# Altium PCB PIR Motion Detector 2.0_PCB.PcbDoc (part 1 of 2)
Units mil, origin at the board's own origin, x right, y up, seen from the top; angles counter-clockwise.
Board outline 6000 x 2200 mil, 4 copper layers (Layer 1 - Top Layer, Layer 2 - GND, Layer 3 - PWR, Layer 4 - Bottom Layer), stack 61.634 mil thick; 136 components, 49 nets, 322 pads, 287 vias.
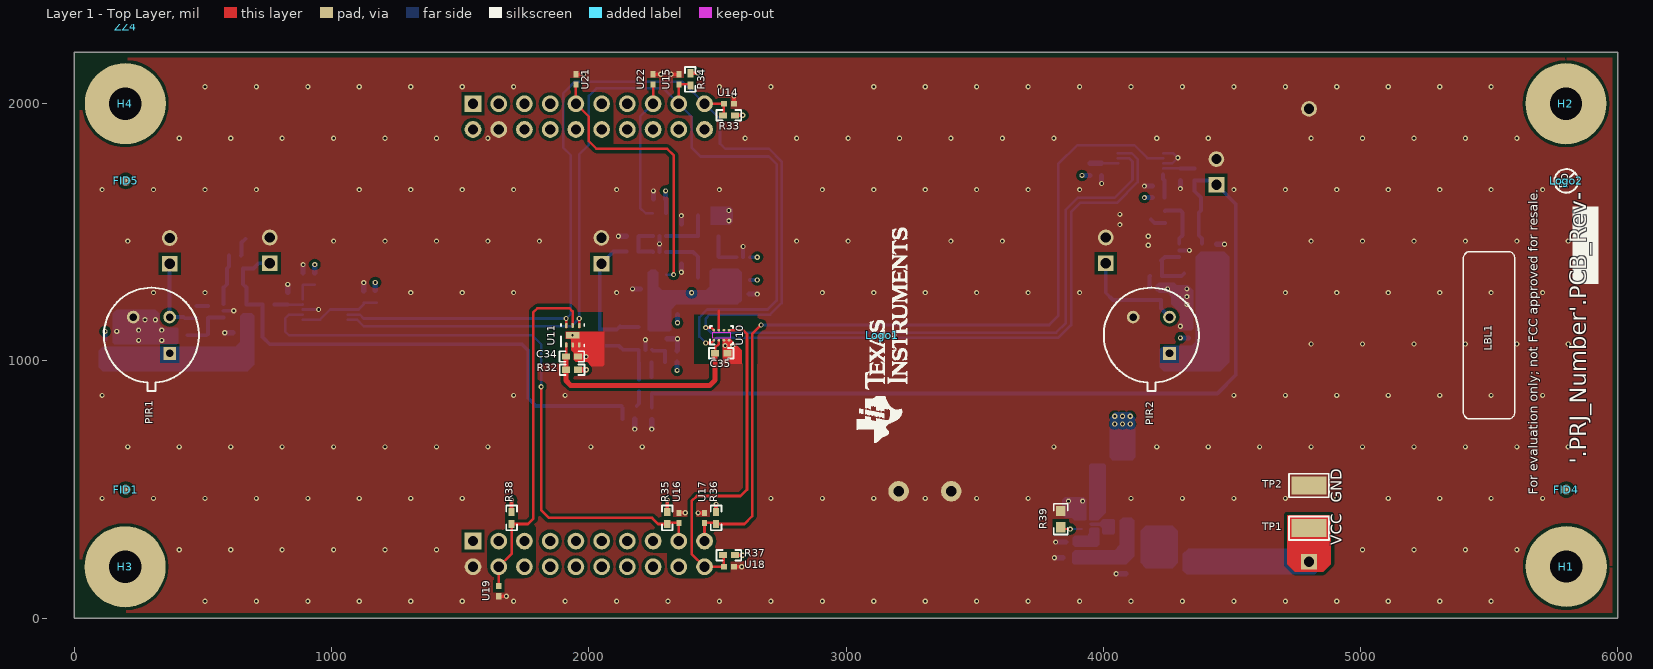
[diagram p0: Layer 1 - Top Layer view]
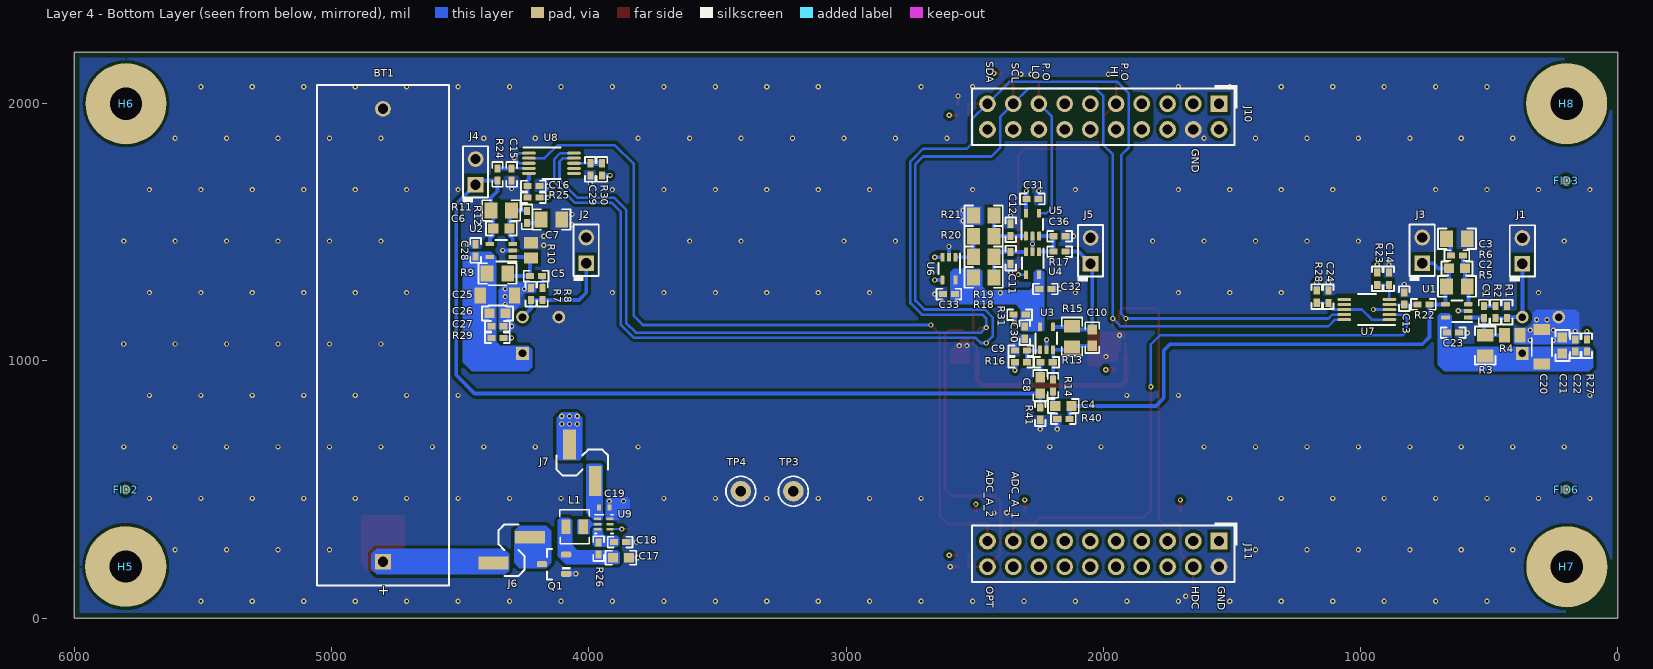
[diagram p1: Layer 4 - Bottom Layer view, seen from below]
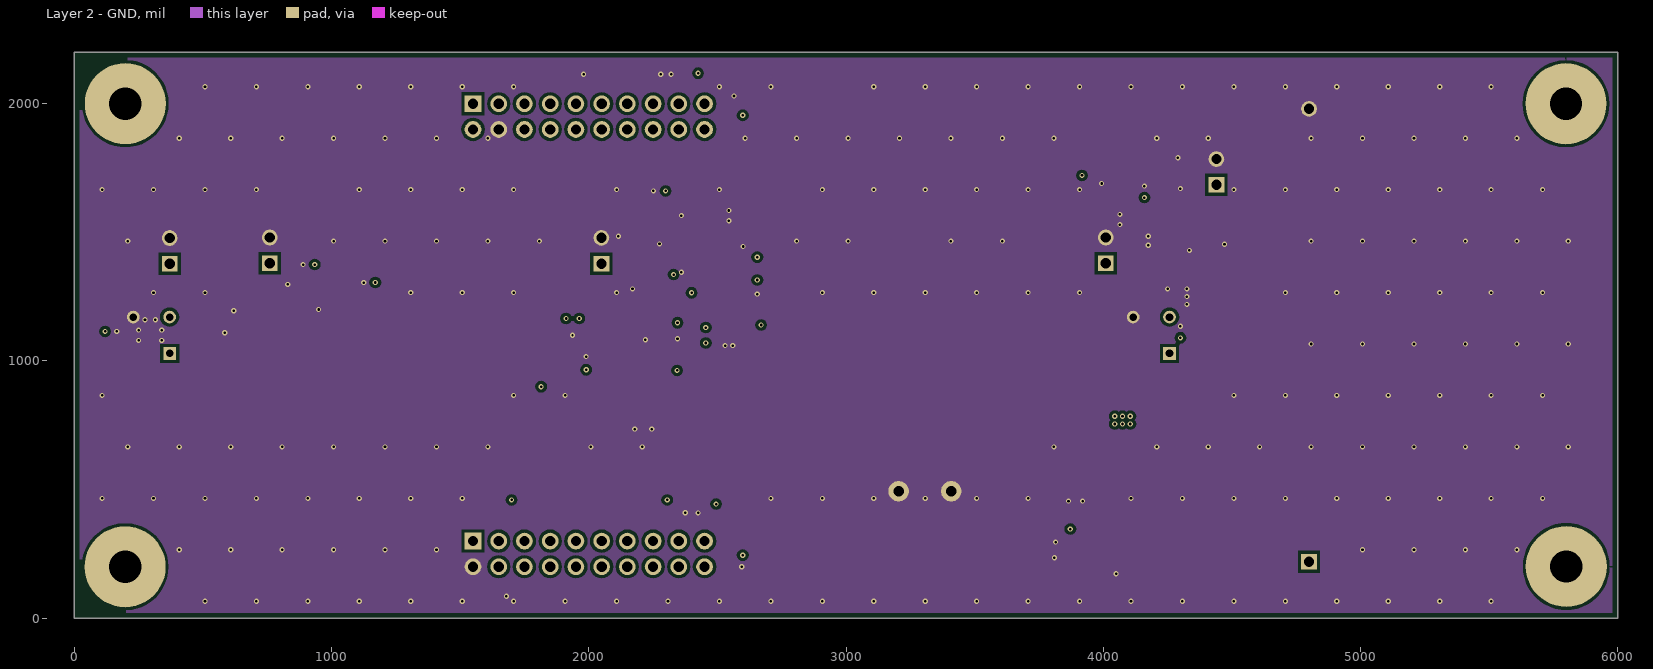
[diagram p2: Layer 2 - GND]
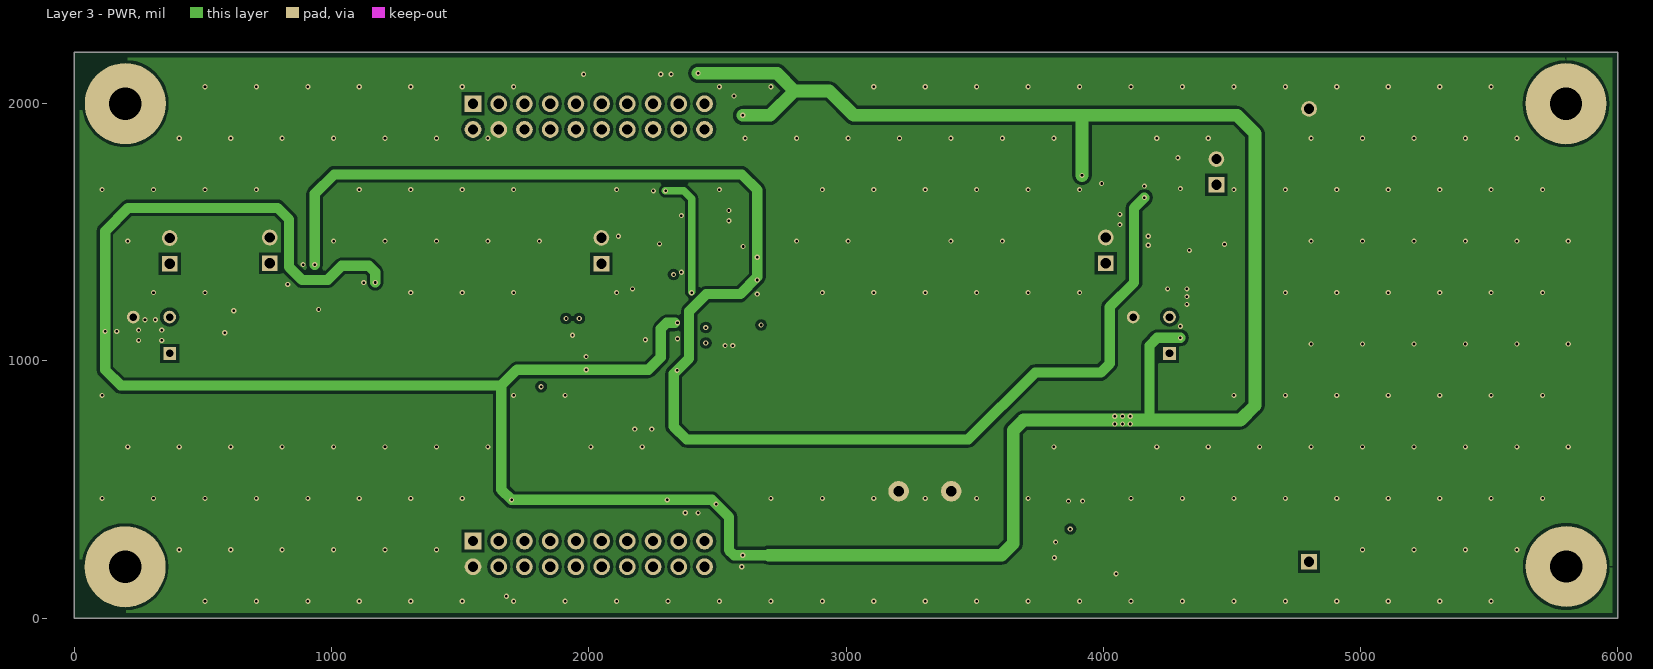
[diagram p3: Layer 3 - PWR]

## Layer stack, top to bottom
Top Solder: solder mask 0.4, Solder Resist, Dk 3.5
Layer 1 - Top Layer: signal copper 1.4
Dielectric 1: prepreg 7, FR-4, Dk 4.2
Layer 2 - GND: signal copper 1.417
Dielectric 2: core 42, FR-4, Dk 4.2
Layer 3 - PWR: signal copper 1.417
Dielectric 3: prepreg 7, FR-4, Dk 4.2
Layer 4 - Bottom Layer: signal copper 1.4
Bottom Solder: solder mask 0.4, Solder Resist, Dk 3.5

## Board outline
0,0 6000,0 6000,2200 0,2200

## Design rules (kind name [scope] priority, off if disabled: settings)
AcuteAngle [All] p1: minimum=4.50000000000000E+0001 checktracksonly=FALSE
AssemblyTestPointUsage [All] p1: valid=2
BoardOutlineClearance BoardOutlineClearance_MountingHoles [OnCopper and InComponentClass('Mounting Holes')] p1: gap=40
BoardOutlineClearance BoardOutlineClearance_Poly [OnCopper and IsPoly] p2: gap=20
BoardOutlineClearance [OnCopper and Not InComponentClass('Logo') and not InComponentClass('FiducialMark') and not InRegion(1000,500,4000,800) and not InPoly] p3: gap=20
Clearance Clearance_U10 [InComponent('U10')] p1: gap=4
Clearance Clearance_Keepouts [((IsTrack Or IsArc) And Not InPoly) And IsFree and IsKeepOut vs ((IsTrack Or IsArc) And Not InPoly) And IsFree and IsKeepOut] p2: gap=0
Clearance Clearance_Poly [InPolygon] p3: gap=12
Clearance [All] p4: gap=7.8
ComponentClearance ComponentClearance_MountingHoles_FiducialMarks [InComponentClass('Mounting Holes') vs InComponentClass('FiducialMark')] p1: gap=50 collisioncheckmode=3 verticalgap=10 showdistances=FALSE
ComponentClearance ComponentClearance_Shunt [InComponentClass('Header') vs InComponentClass('Shunt')] p2: gap=0 collisioncheckmode=3 verticalgap=0 showdistances=FALSE
ComponentClearance ComponentClearance_Logo [InComponentClass('Logo')] p3: gap=50 collisioncheckmode=3 verticalgap=10 showdistances=FALSE
ComponentClearance ComponentClearance_ScrewToNut [(HasFootprint('NY PMS 440 0025 PH')) vs (HasFootprint('Keystone_1902C'))] p4: gap=5 collisioncheckmode=3 verticalgap=10 showdistances=FALSE
ComponentClearance ComponentClearance_MountingHoles [InComponentClass('Mounting Holes')] p5: gap=100 collisioncheckmode=3 verticalgap=100000 showdistances=FALSE
ComponentClearance ComponentClearance_SmallPassives [HasFootprint('0201*') or HasFootprint('0402*') or HasFootprint('0508') or HasFootprint('0603*') or HasFootprint('0612') or HasFootprint('0805*') or HasFootprint('0815*') or HasFootprint('0830*') or HasFootprint('1206*') or HasFootprint('1210*') or HasFootprint('1808*') or HasFootprint('1812*') or HasFootprint('1825*') or HasFootprint('2010*') or HasFootprint('2220*') or HasFootprint('2225*') or HasFootprint('2512*') or HasFootprint('2728*') or HasFootprint('3518*') vs HasFootprint('0201*') or HasFootprint('0402*') or HasFootprint('0508') or HasFootprint('0603*') or HasFootprint('0612') or HasFootprint('0805*') or HasFootprint('0815*') or HasFootprint('0830*') or HasFootprint('1206*') or HasFootprint('1210*') or HasFootprint('1808*') or HasFootprint('1812*') or HasFootprint('1825*') or HasFootprint('2010*') or HasFootprint('2220*') or HasFootprint('2225*') or HasFootprint('2512*') or HasFootprint('2728*') or HasFootprint('3518*')] p6: gap=5 collisioncheckmode=3 verticalgap=10 showdistances=FALSE
ComponentClearance ComponentClearance_THtoSMT [IsThruComponent vs IsSMTComponent] p7: gap=20 collisioncheckmode=3 verticalgap=30 showdistances=FALSE
ComponentClearance ComponentClearance_THtoTH [IsThruComponent vs IsThruComponent] p8: gap=30 collisioncheckmode=3 verticalgap=30 showdistances=FALSE
ComponentClearance [All] p9: gap=10 collisioncheckmode=3 verticalgap=10 showdistances=FALSE
DiffPairsRouting [All] p1: maxlimit=100 minlimit=10 mostfreqgap=10 toplayer_minwidth=15 toplayer_maxwidth=15 toplayer_prefwidth=15 midlayer1_minwidth=15 midlayer1_maxwidth=15 midlayer1_prefwidth=15 midlayer2_minwidth=15 midlayer2_maxwidth=15 midlayer2_prefwidth=15 bottomlayer_minwidth=15 bottomlayer_maxwidth=15 bottomlayer_prefwidth=15 maxuncoupledlength=1000
FabricationTestPointUsage TestPointUsage [All] p1: valid=2 allowmultiple=FALSE
FabricationTestpoint Testpoint [All] p1: side=3 testpointundercomponent=TRUE minsize=40 maxsize=100 preferedsize=60 minholesize=0 maxholesize=40 preferedholesize=32 testpointgrid=1 allowsidetop=TRUE allowsidebottom=TRUE usegrid=TRUE gridtolerance=0.01
FanoutControl Fanout_LCC [IsLCC] p1: bgadir=Out bgaviamode=Centered fanoutstyle=Auto fanoutdirection=Alternating viagrid=1 // Fanout_LCC (Default Rule)
FanoutControl Fanout_BGA [IsBGA] p2: bgadir=Out bgaviamode=Centered fanoutstyle=Auto fanoutdirection=Alternating viagrid=1 // Fanout_BGA (Default Rule)
FanoutControl Fanout_Default [All] p4: bgadir=Out bgaviamode=Centered fanoutstyle=Auto fanoutdirection=Alternating viagrid=1 // Fanout_Default (Default Rule)
FanoutControl Fanout_Small [(CompPinCount < 5)] p5: bgadir=Out bgaviamode=Centered fanoutstyle=Auto fanoutdirection=OutThenIn viagrid=1 // Fanout_Small (Default Rule)
HoleSize [All] p1: absolutevalues=TRUE maxlimit=251 minlimit=7.87 maxpercent=80.000 minpercent=20.000
MinimumAnnularRing MinimumAnnularRing_ThermalPadVias [IsVia and InAnyComponent] p1: minimumring=5.91
MinimumAnnularRing [All] p2: minimumring=5
MinimumSolderMaskSliver MinimumSolderMaskSliver_Logo [InComponentClass('Logo') vs InComponentClass('Logo')] p1: minsoldermaskwidth=0.7
MinimumSolderMaskSliver [All] p2: minsoldermaskwidth=3.94
PlaneConnect [All] p1: planeconnectstyle=Relief reliefexpansion=10 reliefentries=4 reliefconductorwidth=10 reliefairgap=10
PolygonConnect [All] p1: connectstyle=Direct reliefconductorwidth=10 reliefentries=4 polygonreliefangle="90 Angle" airgapwidth=10
RoutingVias ThermalPadVias [IsVia and InAnyComponent] p1: holewidth=7.87 width=19.68 viastyle="Through Hole" minholewidth=7.87 minwidth=19.68 maxholewidth=12.99 maxwidth=23.62
RoutingVias [All] p2: holewidth=16 width=34 viastyle="Through Hole" minholewidth=7.87 minwidth=20 maxholewidth=40 maxwidth=65
SilkToBoardRegionClearance [Not ((IsComment or IsDesignator) And (Hide <> 'False')) and not InRegion(1000,500,4000,800)] p1:
SilkToSilkClearance SilkToSilkClearance_Pb-FreeLogo [(HasFootprint('Pb-Free_Overlay_Medium') OR HasFootprint('Pb-Free_Overlay_Small')) vs (HasFootprint('Pb-Free_Overlay_Medium') OR HasFootprint('Pb-Free_Overlay_Small'))] p1: silktosilkclearance=0
SilkToSilkClearance [All] p2: silktosilkclearance=4
SilkToSolderMaskClearance SilkToComponentPadClearance [IsPad and InAnycomponent] p1: minsilkscreentomaskgap=5 clearancetoexposedcopper=TRUE
SilkToSolderMaskClearance "Silk to Solder Mask Opening" [All] p2: minsilkscreentomaskgap=4 clearancetoexposedcopper=FALSE
SolderMaskExpansion [All] p1: expansion=1.97
Width [All] p1: maxlimit=100 minlimit=6 preferedwidth=10 checkconnectedcopper=TRUE
15 further rules are at their usual default settings.

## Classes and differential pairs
component class "PIR Motion Detector 2.0_PowerSheet": BT1 C17 C18 C19 C20 C21 C22 C23 C24 C25 C26 C27 C28 C29 C30 C31 C32 C33 C34 C35 C? J6 J7 J10 J11 L1 Q1 R26 R27 R28 R29 R30 R31 R32 R33 R34 R35 R36 R37 R38 R39 TP1 TP2 TP3 TP4 U9 U10 U11 U14 U15 U16 U17 U18 U19
component class "PIR Motion Detector 2.0_BlankSheet": ADC1 C1 C2 C3 C4 C5 C6 C7 C8 C9 C10 C11 C12 C13 C14 C15 C16 C36 C? J1 J2 J3 J4 J5 PIR1 PIR2 R1 R2 R3 R4 R5 R6 R7 R8 R9 R10 R11 R12 R13 R14 R15 R16 R17 R18 R19 R20 R21 R22 R23 R24 R25 R40 R41 R? U1 U2 U3 U4 U5 U6 U7 U8 U21 U22 U?
component class "Mounting Holes": H1 H2 H3 H4
component class Logo: Logo1
component class "PIR Motion Detector 2.0_EVM_Hardware": FID1 FID2 FID3 FID4 FID5 FID6 H1 H2 H3 H4 H5 H6 H7 H8 LBL1 Logo1 Logo2 Logo3 ZZ1 ZZ2 ZZ3 ZZ4
component class FiducialMark: FID1 FID2 FID3 FID4 FID5 FID6
component class AssemblyNote: ZZ1 ZZ2 ZZ3 ZZ4
component class Label: LBL1
component class Header: J1 J2 J3 J4 J5 J6 J7 J10 J11

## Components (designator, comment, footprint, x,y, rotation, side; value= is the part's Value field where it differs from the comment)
BT1 "2466" Keystone_2466 4800,1100 r90 bottom locked
C1 "C1005X5R1A105K050BB" 0402 520,1190 r90 bottom
C2 "06035A101FAT2A" 0603 625,1360 r180 bottom
C3 "C2012X5R1A336M125AC" 0805_HV 625,1475 r0 bottom
C4 "GRM188R61A106ME69D" 0603 2155,825 r180 bottom
C5 "C1005X5R1A105K050BB" 0402 4205,1330 r180 bottom
C6 "06035A101FAT2A" 0603 4340,1515 r180 bottom
C7 "C2012X5R1A336M125AC" 0805_HV 4145,1550 r0 bottom
C8 "GRM188R61A106ME69D" 0603 2245,905 r270 bottom
C9 "C1005X7R1H104K050BB" 0402 2320,1040 r0 bottom
C10 "GRM1885C1H151JA01D" 0603 2042.54,1090.75 r270 bottom
C11 "C1005X7R1H104K050BB" 0402 2360,1400 r270 bottom
C12 "C1005X7R1H104K050BB" 0402 2360,1510 r90 bottom
C13 "GRM1555C1H331FA01J" 0402 829.76,1242.62 r90 bottom
C14 "C1005X7R1H104K050BB" 0402 889.67,1319.63 r90 bottom
C15 "C1005X5R1A105K050BB" 0402 4300,1725 r270 bottom
C16 "C1005X7R1H104K050BB" 0402 4215,1680 r180 bottom
C17 "GRM188R60J106ME47D" 0603 3875,235 r180 bottom
C18 "GRM1555C1H331FA01J" 0402 3877.83,295.83 r180 bottom
C19 "GRM155R60G106ME44D" 0402_070 3940,430 r180 bottom
C20 "C3216X5R1A107M160AC" 1206_190 295,1055 r90 bottom
C21 "06033C105KAT2A" 0603 215,1060 r90 bottom
C22 "0402YC104KAT2A" 0402 165,1060 r90 bottom
C23 "0402YC104KAT2A" 0402 640,1110 r180 bottom
C24 "0402YC104KAT2A" 0402 1125,1249.63 r90 bottom
C25 "C3216X5R1A107M160AC" 1206_190 4355,1255 r180 bottom
C26 "06033C105KAT2A" 0603 4355,1185 r180 bottom
C27 "0402YC104KAT2A" 0402 4355,1135 r180 bottom
C28 "0402YC104KAT2A" 0402 4440,1430 r90 bottom
C29 "0402YC104KAT2A" 0402 3993.78,1745 r270 bottom
C30 "0402YC104KAT2A" 0402 2305,1110 r270 bottom
C31 "0402YC104KAT2A" 0402 2275,1630 r180 bottom
C32 "0402YC104KAT2A" 0402 2225,1280 r180 bottom
C33 "0402YC104KAT2A" 0402 2600,1260 r0 bottom
C34 "0402YC104KAT2A" 0402 1934.58,1017.21 r0 top
C35 "0402YC104KAT2A" 0402 2515,1030 r0 top
C36 "GRM1555C1H331FA01J" 0402 2170,1485 r180 bottom
FID1 "Fiducial" Fiducial10-20 200,500 r0 top
FID2 "Fiducial" Fiducial10-20 5800,500 r180 bottom
FID3 "Fiducial" Fiducial10-20 200,1700 r180 bottom
FID4 "Fiducial" Fiducial10-20 5800,500 r0 top
FID5 "Fiducial" Fiducial10-20 200,1700 r0 top
FID6 "Fiducial" Fiducial10-20 200,500 r180 bottom
H1 "NY PMS 440 0025 PH" "NY PMS 440 0025 PH"#1 5800,200.98 r0 top locked
H2 "NY PMS 440 0025 PH" "NY PMS 440 0025 PH"#1 5798.95,2000 r0 top locked
H3 "NY PMS 440 0025 PH" "NY PMS 440 0025 PH"#1 197.56,200 r0 top locked
H4 "NY PMS 440 0025 PH" "NY PMS 440 0025 PH"#2 198.95,2000 r0 top locked
H5 "1902C" Keystone_1902C 5800,200.98 r180 bottom locked
H6 "1902C" Keystone_1902C 5798.95,2000 r180 bottom locked
H7 "1902C" Keystone_1902C 197.56,200 r180 bottom locked
H8 "1902C" Keystone_1902C 198.95,2000 r180 bottom locked
J1 "HMTSW-102-07-G-S-240" SAMTEC_HMTSW-102-07-G-S-240 370.57,1427.95 r90 bottom
J2 "HMTSW-102-07-G-S-240" SAMTEC_HMTSW-102-07-G-S-240 4010,1430 r90 bottom
J3 "HMTSW-102-07-G-S-240" SAMTEC_HMTSW-102-07-G-S-240 760,1430 r90 bottom
J4 "HMTSW-102-07-G-S-240" SAMTEC_HMTSW-102-07-G-S-240 4440,1735 r90 bottom
J5 "HMTSW-102-07-G-S-240" SAMTEC_HMTSW-102-07-G-S-240 2049.19,1428.44 r90 bottom
J6 "87898-0204" Molex_87898-0204 4300,265 r90 bottom
J7 "87898-0204" Molex_87898-0204 4025,605 r0 bottom
J10 "PEC10DAAN" SULLINS_PEC10DAAN 2000,1950 r270 bottom locked
J11 "PEC10DAAN" SULLINS_PEC10DAAN 2000,250 r270 bottom locked
L1 "VLF302510MT-4R7M" VLF302510MT 4055,355 r180 bottom
LBL1 "Size: 0.65\" x 0.20 \"" Label_650x200 5500,1100 r90 top
Logo1 "Texas Instruments" TI_Stacked_Overlay_Small 3140,1100 r90 top
Logo2 "Pb-Free Symbol" Pb-Free_Overlay_Small 5800,1700 r90 top
Logo3 "FCC disclaimer" FCC_disclaimer 2350,3380 r0 top
PIR1 "IRA-E700ST0" Murata_IRA-E700ST0 300,1100 r90 top locked
PIR2 "IRA-E700ST0" Murata_IRA-E700ST0 4187,1100 r90 top locked
Q1 "SI2323DS" SOT-23 4135,210 r0 bottom
R1 "CRCW04021M30FKED" 0402 430,1190 r270 bottom
R2 "CRCW04020000Z0ED" 0402 475,1190 r90 bottom
R3 "RMCF0805JT15M0" 0805_HV 515,1060 r270 bottom
R4 "RMCF0805JT15M0" 0805L 410,1100 r0 bottom
R5 "RMCF0805JT15M0" 0805_HV 625,1290 r0 bottom
R6 "CRCW040240K2FKED" 0402 625,1410 r180 bottom
R7 "CRCW04021M30FKED" 0402 4225,1260 r270 bottom
R8 "CRCW04020000Z0ED" 0402 4180,1260 r90 bottom
R9 "RMCF0805JT15M0" 0805_HV 4355,1340 r0 bottom
R10 "RMCF0805JT15M0" 0805L 4225,1430 r270 bottom
R11 "RMCF0805JT15M0" 0805_HV 4340,1585 r0 bottom
R12 "CRCW040240K2FKED" 0402 4240,1560 r90 bottom
R13 "CRCW0402150KFKED" 0402 2220,995 r180 bottom
R14 "CRCW0402150KFKED" 0402 2195,905 r90 bottom
R15 "CRCW080510M0FKEA" 0805_HV 2121.65,1094.99 r90 bottom
R16 "CRCW04020000Z0ED" 0402 2320,995 r180 bottom
R17 "CRCW0402100KFKED" 0402 2170,1425 r0 bottom
R18 "RMCF0805JT15M0" 0805_HV 2465,1325 r0 bottom
R19 "RMCF0805JT15M0" 0805_HV 2465,1405 r180 bottom
R20 "RMCF0805JT15M0" 0805_HV 2465,1485 r0 bottom
R21 "RMCF0805JT15M0" 0805_HV 2465,1565 r180 bottom
R22 "CRCW0402100KFKED" 0402 755,1220 r0 bottom
R23 "CRCW04020000Z0ED" 0402 934.67,1319.63 r270 bottom
R24 "CRCW04020000Z0ED" 0402 4355,1725 r90 bottom
R25 "CRCW04020000Z0ED" 0402 4215,1635 r0 bottom
R26 "CRCW04020000Z0ED" 0402 3961.84,270.83 r90 bottom
R27 "CRCW040210R0FKED" 0402 120,1060 r270 bottom
R28 "CRCW040210R0FKED" 0402 1170,1250 r270 bottom
R29 "CRCW040210R0FKED" 0402 4355,1090 r0 bottom
R30 "CRCW040210R0FKED" 0402 3948.78,1745 r90 bottom
R31 "CRCW040210R0FKED" 0402 2325,1180 r180 bottom
R32 "CRCW040210R0FKED" 0402 1935,965.78 r180 top
R33 "CRCW040210K0JNED" 0402 2545,1955 r0 top
R34 "CRCW040210K0JNED" 0402 2395,2095 r90 top
R35 "CRCW040210K0JNED" 0402 2305,390 r90 top
R36 "CRCW040210K0JNED" 0402 2495,390 r90 top
R37 "CRCW040210K0JNED" 0402 2545,245 r0 top
R38 "CRCW040210K0JNED" 0402 1700,390 r90 top
R39 "CRCW060310M0JNEA" 0603 3835,385 r270 top
R40 "CRCW040210K0JNED" 0402 2155,775 r180 bottom
R41 "CRCW040210K0JNED" 0402 2245,795 r90 bottom
TP1 "5015" Testpoint_Keystone_Miniature 4800,350 r0 top
TP2 "5015" Testpoint_Keystone_Miniature 4800,515.51 r180 top
TP3 "5001" Keystone5001 3204.69,493.64 r90 bottom
TP4 "5001" Keystone5001 3409.03,493.64 r90 bottom
U1 "OPA349SA/3K" DCK0005A_N 625,1195 r0 bottom
U2 "OPA349SA/3K" DCK0005A_N 4340,1430 r0 bottom
U3 "TLV369IDCKR" DCK0005A_N 2220.12,1088.11 r90 bottom
U4 "TLV3691IDCKR" DCK0005A_N 2275,1380 r270 bottom
U5 "TLV3691IDCKR" DCK0005A_N 2275,1530 r90 bottom
U6 "TLV369IDCKR" DCK0005A_N 2600,1359.15 r270 bottom
U7 "ADS1114IDGSR" DGS0010A_N 975,1200 r0 bottom
U8 "ADS1114IDGSR" DGS0010A_N 4144.96,1768.61 r180 bottom
U9 "TPS610981DSER" DSE0006A 3941.62,366.15 r180 bottom
U10 "HDC1010YPAR" YPA0008AGAE 2515.79,1100 r90 top locked
U11 "OPT3002DNPR" DNP0006A 1937.34,1100 r90 top locked
U14 "TPD1E10B06DPYR" DPY0002A 2545,2000 r0 top
U15 "TPD1E10B06DPYR" DPY0002A 2350,2095 r90 top
U16 "TPD1E10B06DPYR" DPY0002A 2350,390 r90 top
U17 "TPD1E10B06DPYR" DPY0002A 2450,390 r90 top
U18 "TPD1E10B06DPYR" DPY0002A 2545,200 r0 top
U19 "TPD1E10B06DPYR" DPY0002A 1650,105 r270 top
U21 "TPD1E10B06DPYR" DPY0002A 1950,2095 r90 top
U22 "TPD1E10B06DPYR" DPY0002A 2250,2095 r90 top
ZZ1 "This Assembly Note is for PCB labels only" AssemblyNoteLabel 200,2600 r0 top
ZZ2 "These assemblies are ESD sensitive, ESD precautions shall be observed." AssemblyNote 200,2500 r0 top
ZZ3 "These assemblies must be clean and free from flux and all contaminants. Use of no clean flux is not acceptable." AssemblyNote 200,2400 r0 top
ZZ4 "These assemblies must comply with workmanship standards IPC-A-610 Class 2, unless otherwise specified." AssemblyNote 200,2300 r0 top

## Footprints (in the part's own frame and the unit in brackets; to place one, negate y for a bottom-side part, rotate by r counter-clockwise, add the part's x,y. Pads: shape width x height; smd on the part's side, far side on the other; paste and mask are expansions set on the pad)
0402 [mm] "0402 from SM-752 data"
  rect 0.8x0.6 smd: 1(-0.6,0) 2(0.6,0)
  silkscreen extent -1.22,-0.52 1.22,0.52, body extent -0.55,-0.3 0.55,0.3, height 0.6
0402_070 [mil] "SMD, 2-Leads, Body 1.2x0.7mm, Height 0.7mm"
  rect 15x24 smd: 1(-20,0) 2(20,0)
  body extent -24,-14 24,14, height 28
0603 [mm] "0603 from SM-752 data"
  rect 1x0.95 smd: 1(-0.8,0) 2(0.8,0)
  silkscreen extent -1.52,-0.69 1.52,0.69, body extent -0.87,-0.47 0.87,0.47, height 1
0805_HV [mil] "0805 with 30mil clearance between pads"
  rect 50x63 smd: 1(-40,0) 2(40,0)
  silkscreen extent -74,-40 74,40, body extent -43,-29 43,29, height 57
0805L [mm] "0805 from SM-752 data"
  rect 1.1x1.4 smd: 1(-0.75,0) 2(0.75,0)
  body extent -1.1,-0.72 1.1,0.72, height 1.45
1206_190 [mm] "1206_190"
  rect 1.1x1.6 smd: 1(-1.7,0) 2(1.7,0)
  silkscreen extent -0.9,-1 0.9,1, body extent -1.75,-0.95 1.75,0.95, height 1.9
AssemblyNote [mil] "Assembly Note"
AssemblyNoteLabel [mil] "Assembly Note for PCB Labels"
DCK0005A_N [mm] "SOT353, 5-Leads, Body 2x1.3mm, Pitch 0.65mm, Lead Span 2.1mm, IPC Medium Density"
  rrect25% 0.85x0.4 smd: 1(-1.125,0.65) 2(-1.125,0) 3(-1.125,-0.65) 4(1.125,-0.65) 5(1.125,0.65)
  silkscreen extent -1.48,-1.02 0.55,1.1, body extent -1.14,-1 1.14,1, height 1.09
DGS0010A_N [mm] "TSSOP, 10-Leads, Body 3x3mm, Pitch 0.5mm, IPC Medium Density"
  oval 1.35x0.3 smd: 1(-2.225,1) 2(-2.225,0.5) 3(-2.225,0) 4(-2.225,-0.5) 5(-2.225,-1) 6(2.225,-1) 7(2.225,-0.5) 8(2.225,0) 9(2.225,0.5) 10(2.225,1)
  silkscreen extent -2.75,-1.55 0.9,1.55, body extent -2.45,-1.5 2.45,1.5, height 0.96
DNP0006A [mm] "DFN-6 2x2mm"
  oval 0.5x0.25 smd: 1(-0.95,0.65) 2(-0.95,0) 3(-0.95,-0.655) 4(0.95,-0.65) 5(0.95,0) 6(0.95,0.65)
  rect 0.65x1.35 smd paste-0.5: 7(0,0)
  silkscreen extent -1.12,-1.15 1.12,1.15, body extent -1,-1 1,1, height 0.64
DPY0002A [mm] "R-PX2SON-N2"
  rect 0.6x0.5 smd: 1(-0.5,0) 2(0.5,0)
  body extent -0.55,-0.35 0.55,0.35, height 0.4
DSE0006A [mm] "TI recommended land pattern"
  rect 0.66x0.25 smd: 1(-0.62,0.5)
  rect 0.7x0.25 smd: 2(-0.6,0) 3(-0.6,-0.5) 4(0.6,-0.5) 5(0.6,0) 6(0.6,0.5)
  Layer 1 - Top Layer region: -0.3,0.625 -0.25,0.625 -0.15,0.525 -0.15,0.375 -0.3,0.375
  silkscreen extent -0.9,-0.92 0.9,0.92, body extent -0.77,-0.77 0.77,0.77, height 0.8
FCC_disclaimer [mil]
Fiducial10-20 [mm]
  round 1 smd mask+0.5: 1(0,0)
Keystone5001 [mil] "For Keystone 500x miniature loop terminals"
  round 80 hole 40: 1(0,0)
  silkscreen extent -58,-58 58,58, body extent -49,-49 49,49, height 182
Keystone_1902C [mil] "Hex Standoff, 4-40 threaded, nylon"
  body extent -145,-126 146,126, height 501
Keystone_2466 [mm] "TH, 2-Leads, Body 49.99x13mm, Pin Spacing 44.7mm"
  rect 1.55x1.55 hole 1.02: 1(-22.35,0)
  round 1.55 hole 1.02: 2(22.35,0)
  silkscreen extent -24.7,-6.5 24.7,6.5, body extent -24.7,-6.5 24.7,6.5, height 12.7
Label_650x200 [mil] "Thermal Transfer Label"
  silkscreen extent -325,-100 325,100, body extent -325,-100 325,100, height 1
Molex_87898-0204 [mm] "Header, 2.54 mm, 2x1, R/A, SMT"
  rect 1.27x2.96 smd: 1(-1.27,1.8) 2(1.27,-1.8)
  silkscreen extent -2.54,-1.27 2.54,1.27, body extent -2.54,-2.4 2.54,2.4, height 9.65
Murata_IRA-E700ST0 [mm] "TH, 3-Leads, Dia 9.2mm"
  rect 1.25x1.25 hole 0.75: 1(-1.796,-1.796)
  round 1.25 hole 0.75: 2(1.796,-1.796) 3(1.796,1.796)
  silkscreen extent -5.5,-4.7 4.7,4.7, body extent -5.5,-4.7 4.7,4.7, height 4.9
"NY PMS 440 0025 PH"#1 [mm] "4-40 nylon screw and mounting hole"
  round 8 hole 3.2: 1(0,0)
  body extent -3.3,-3.3 3.3,3.3, height 2.69
"NY PMS 440 0025 PH"#2 [mm] "4-40 nylon screw and mounting hole"
  round 8 hole 3.2: 1(-0.018,0.009)
  body extent -3.3,-3.3 3.3,3.3, height 2.69
Pb-Free_Overlay_Small [mil]
  silkscreen extent -46,-46 46,46
SAMTEC_HMTSW-102-07-G-S-240 [mm] "Header, 2.54mm, 2x1, TH"
  rect 1.55x1.55 hole 1.02: 1(-1.27,0)
  round 1.55 hole 1.02: 2(1.27,0)
  silkscreen extent -3.01,-1.24 2.54,1.27, body extent -2.54,-1.27 2.54,1.27, height 8.64
SOT-23 [mm] "SOT23, 3-Leads, Body 2.9x1.3mm, Pitch 0.95mm, Lead Span 2.5mm, IPC Medium Density"
  rrect50% 1x0.6 smd: 1(-1.2,0.95) 2(-1.2,-0.95) 3(1.2,0)
  silkscreen extent -1.62,-1.5 0.7,1.5, body extent -1.16,-1.45 1.21,1.45, height 1
SULLINS_PEC10DAAN [mm] "SULLINS"
  rect 1.65x1.65 hole 1.016: 1(-1.27,11.43)
  round 1.65 hole 1.016: 2(1.27,11.43) 3(-1.27,8.89) 4(1.27,8.89) 5(-1.27,6.35) 6(1.27,6.35) 7(-1.27,3.81) 8(1.27,3.81) 9(-1.27,1.27) 10(1.27,1.27) 11(-1.27,-1.27) 12(1.27,-1.27) 13(-1.27,-3.81) 14(1.27,-3.81) 15(-1.27,-6.35) 16(1.27,-6.35) 17(-1.27,-8.89) 18(1.27,-8.89) 19(-1.27,-11.43) 20(1.27,-11.43)
  silkscreen extent -3.11,-12.96 2.79,13.25, body extent -2.79,-12.96 2.79,12.96, height 9.08
Testpoint_Keystone_Miniature [mil] "Miniature SMT test point"
  rect 135x70 smd: 1(0,0)
  silkscreen extent -78,-46 78,45, body extent -52,-20 52,20, height 61
TI_Stacked_Overlay_Small [mil]
  silkscreen extent -418,-98 418,98
VLF302510MT [mm] "TDK"
  rect 0.9x1.45 smd: 1(-0.85,0) 2(0.85,0)
  silkscreen extent -1.45,-1.68 1.45,1.68, body extent -1.35,-1.6 1.35,1.6, height 1
YPA0008AGAE [mm] "BGA, 8-Leads, Body 2.04x1.59mm, Pitch 0.5mm"
  round 0.263 smd paste-0.14: A1(-0.5,0.75) A2(0.5,0.75) B1(-0.5,0.25) B2(0.5,0.25) C1(-0.5,-0.25) C2(0.5,-0.25) D1(-0.5,-0.75) D2(0.5,-0.75)
  Layer 1 - Top Layer keep-out region: -0.249,-0.9 0.251,-0.9 0.251,0.9 -0.249,0.9
  silkscreen extent -0.91,-1.14 0.91,1.14, body extent -0.81,-1.04 0.81,1.04, height 0.68

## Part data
BT1: "HOLDER BATTERY AAA, TH"
C1 C5: "CAP, CERM, 1 µF, 10 V, +/- 10%, X5R, 0402"
C2 C6: "CAP, CERM, 100 pF, 50 V, +/- 1%, C0G/NP0, 0603"
C3 C7: "CAP, CERM, 33 µF, 10 V, +/- 20%, X5R, 0805"
C4 C8: "CAP, CERM, 10 µF, 10 V, +/- 20%, X5R, 0603"
C9 C11 C12 C14 C16: "CAP, CERM, 0.1 µF, 50 V, +/- 10%, X7R, 0402"
C10: "CAP, CERM, 150 pF, 50 V, +/- 5%, C0G/NP0, 0603"
C13 C36: "CAP, CERM, 330 pF, 50 V, +/- 1%, C0G/NP0, 0402"
C15: library part GRM1555C1H331FA01J, "CAP, CERM, 330 pF, 50 V, +/- 1%, C0G/NP0, 0402"
C17: "CAP, CERM, 10 µF, 6.3 V, +/- 20%, X5R, 0603"
C18: library part GRM155R61A105KE15D, "CAP, CERM, 1 µF, 10 V, +/- 10%, X5R, 0402"
C19: "CAP, CERM, 10 µF, 4 V, +/- 20%, X5R, 0402"
C20 C25: "CAP, CERM, 100 µF, 10 V, +/- 20%, X5R, 1206_190"
C21 C26: "CAP, CERM, 1 µF, 25 V, +/- 10%, X7R, 0603"
C22 C23 C24 C27 C28 C29 C30 C31 C32 C33 C34 C35: "CAP, CERM, 0.1 µF, 16 V, +/- 10%, X7R, 0402"
FID1 FID2 FID3 FID4 FID5 FID6: "Fiducial mark.  There is nothing to buy or mount."
H1 H2 H3 H4: "Machine Screw, Round, #4-40 x 1/4, Nylon, Philips panhead"
H5 H6 H7 H8: "Standoff, Hex, 0.5\"L #4-40 Nylon"
J1 J2 J3 J4 J5: "Header, 100mil, 2x1, Gold, TH"
J6 J7: "Header, 2.54 mm, 2x1, Gold, R/A, SMT"
J10 J11: "Header, 100mil, 10x2, TH"
L1: "Inductor, Shielded, Ferrite, 4.7 µH, 0.86 A, 0.168 ohm, SMD"
LBL1: library part THT-14-423-10, "Thermal Transfer Printable Labels, 0.650\" W x 0.200\" H - 10,000 per roll"
Logo1: library part TI_Logo, "Texas Instrument Corporate Signature"
Logo2: library part Pb-Free
Logo3: library part FCC_disclaimer, "FCC_disclaimer"
PIR1 PIR2: "Pyroelectric Infrared Sensor, TH"
Q1: "MOSFET, P-CH, -20 V, -3.7 A, SOT-23"
R1 R7: "RES, 1.30 M, 1%, 0.063 W, 0402"
R2 R8 R16 R23 R25: "RES, 0, 5%, 0.063 W, 0402"
R3 R4 R5 R9 R10 R11 R18 R19 R20 R21: "RES, 15 M, 5%, 0.125 W, AEC-Q200 Grade 0, 0805"
R6 R12: "RES, 40.2 k, 1%, 0.063 W, 0402"
R13 R14: "RES, 150 k, 1%, 0.063 W, 0402"
R15: "RES, 10.0 M, 1%, 0.125 W, 0805"
R17 R22: "RES, 100 k, 1%, 0.063 W, 0402"
R24: library part CRCW0402100KFKED, "RES, 100 k, 1%, 0.063 W, 0402"
R26: library part CRCW0402300RJNED, "RES, 300, 5%, 0.063 W, 0402"
R27 R28 R29 R30 R31 R32: "RES, 10.0, 1%, 0.063 W, 0402"
R33 R34 R35 R36 R37 R38 R40 R41: "RES, 10 k, 5%, 0.063 W, 0402"
R39: "RES, 10 M, 5%, 0.1 W, 0603"
TP1 TP2: "Test Point, Miniature, SMT"
TP3 TP4: "Test Point, Miniature, Black, TH"
U1 U2: "1 uA, Rail-to-Rail, CMOS Operational Amplifier, 1.8 to 5.5 V, 0 to 85 degC, 5-pin SOT23 (DCK0005A), Green (RoHS & no Sb/Br)"
U3 U6: "Cost-Optimized, 800-nA, 1.8-V, Rail-to-Rail I/O Operational Amplifier with Zero-Crossover Distortion, DCK0005A (SOT-5)"
U4 U5: "0.9-V to 6.5-V, Nanopower Comparator, DCK0005A (SOT-5)"
U7 U8: "Ultra-Small, Low-Power, I2C-Compatible, 860-SPS, 16-Bit ADCs With Internal Reference, Oscillator, and Programmable Comparator, DGS0010A (VSSOP-10)"
U9: "Ultra-Low Quiescent Current Synchronous Boost with Integrated LDO/Load Switch, DSE0006A (WSON-6)"
U10: "Low Power, High Accuracy Digital Humidity Sensor with Temperature Sensor, YPA0008AGAE (DSBGA-8)"
U11: "OPT3002 Light to Digital Sensor, DNP0006A (USON-6)"
U14 U15 U16 U17 U18 U19 U21 U22: "ESD in 0402 Package with 10 pF Capacitance and 6 V Breakdown, 1 Channel, -40 to +125 degC, 2-pin X2SON (DPY), Green (RoHS & no Sb/Br)"
ZZ1: library part AssemblyNoteLabel
ZZ2 ZZ3 ZZ4: library part AssemblyNote

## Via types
v1: diameter 20, hole 10, Layer 1 - Top Layer to Layer 4 - Bottom Layer, tented both sides, 286 vias
v2: diameter 19.68, hole 7.87, Layer 1 - Top Layer to Layer 4 - Bottom Layer, 1 vias

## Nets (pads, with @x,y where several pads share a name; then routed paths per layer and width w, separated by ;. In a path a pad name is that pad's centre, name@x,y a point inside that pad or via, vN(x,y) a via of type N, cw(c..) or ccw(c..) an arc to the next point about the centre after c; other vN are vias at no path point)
ADC1ALERT: J11.17 R35.1 U7.2 U16.1 | length 2413.6
  Layer 1 - Top Layer w10: v1(1815,900) 1815,420 1845,390 2246.38,390 2270,366.38 R35.1@2305,366.38 2308.94,370.32 U16.1@2350,370.32 J11.17@2350,300
  Layer 4 - Bottom Layer w10: U7.2@887.4,1180.32 835.32,1180.32 820,1165 820,1115 835,1100 1780,1100 1815,1065 v1(1815,900)
ADC2ALERT: J11.19 R36.1 U8.2 U17.1 | length 3246.6
  Layer 1 - Top Layer w10: J11.19@2450,300 U17.1@2450,370.32 2491.06,370.32 R36.1@2495,366.38 2605,366.38 2635,396.38 2635,1105 v1(2670,1140)
  Layer 4 - Bottom Layer w10: v1(2670,1140) 3790,1140 3825,1175 3825,1765 3899.47,1839.47 4120.53,1839.47 4171.71,1788.29 U8.2@4232.56,1788.29
GND: BT1.2 C3.1 C7.1 C9.2 C11.2 C12.2 C13.2 C14.2 C15.2 C16.2 C17.2 C18.2 C19.2 C20.2 C21.2 C22.2 C23.2 C24.2 C25.2 C26.2 C27.2 C28.2 C29.2 C30.2 C31.2 C32.2 C33.2 C34.2 C35.2 C36.2 J1.2 J2.2 J3.2 J4.2 J5.2 J10.4 J11.2 PIR1.3 PIR2.3 Q1.1 R1.1 R4.1 R7.1 R10.1 R21.1 R39.1 R40.1 R41.1 TP2.1 TP3.1 TP4.1 U1.2 U2.2 U3.2 U4.2 U5.2 U6.2 U7.3 U8.1 U8.3 U9.6 U10.B2 U10.C1 U10.D1 U11.2 U11.3 U11.7 U14.2 U15.2 U16.2 U17.2 U18.2 U19.2 U21.2 U22.2 | length 1432.9
  Layer 1 - Top Layer w10: U10.B2@2505.95,1119.69 2505.95,1194.74
  Layer 1 - Top Layer w15: U19.2@1650,85.32 v1(1680,85.32) ; U21.2@1950,2114.68 v1(1980,2114.68) ; U22.2@2250,2114.68 v1(2280,2114.68) ; v1(2320,2114.69) U15.2@2350,2114.69 ; U16.2@2350,409.69 2350.32,410 v1(2375,410) ; v1(2425,409.68) U17.2@2450,409.68 ; U18.2@2564.68,200 v1(2594.68,200) ; U14.2@2564.68,2000 v1(2564.68,2030)
  Layer 4 - Bottom Layer w10: U7.3@887.4,1200 v1(950,1200) ; U8.3@4232.56,1768.61 4268.61,1768.61 v1(4290,1790) 4272.02,1807.98 U8.1@4232.56,1807.98
  Layer 4 - Bottom Layer w15: U1.2@580.71,1195 v1(620,1195) ; U3.2@2220.12,1043.23 v1(2220.12,1082.52) ; U4.2@2275,1424.29 v1(2275,1455) U5.2@2275,1485.71 ; U6.2@2600,1403.44 v1(2600,1445) ; U2.2@4295.71,1430 v1(4335,1430)
  Layer 4 - Bottom Layer w20: v1(585,1110) C23.2@616.38,1110 ; C13.2@829.76,1266.24 v1(829.76,1297.62) ; C14.2@889.67,1343.25 v1(889.67,1374.63) ; C24.2@1125,1273.25 v1(1125,1304.63) ; v1(2115,1485) C36.2@2146.38,1485 ; v1(2170,1280) C32.2@2201.38,1280 ; v1(2178.62,735) R40.1@2178.62,775 ; v1(2245,735) R41.1@2245,771.38 ; C31.2@2251.38,1630 v1(2251.38,1661.38) ; C30.2@2305,1086.38 v1(2345,1086.38) 2345,1041.38 C9.2@2343.62,1040 ; v1(2360,1345) C11.2@2360,1376.38 ; C12.2@2360,1533.62 v1(2360,1565) ; C33.2@2623.62,1260 v1(2655,1260) ; v1(3810,235) C17.2@3843.5,235 ; v1(3815,295.83) C18.2@3854.21,295.83 ; v1(3993.78,1690) C29.2@3993.78,1721.38 ; v1(4050,172.6) Q1.1@4087.76,172.6 ; v1(4160,1680) C16.2@4191.38,1680 ; v1(4300,1670) C15.2@4300,1701.38 ; C28.2@4440,1453.62 v1(4471.38,1453.62)
  other v1: 508,66 708,66 908,66 1108,66 1308,66 1508,66 1708,66 1908,66 2108,66 2308,66 2508,66 2708,66 2908,66 3108,66 3308,66 3508,66 3708,66 3908,66 4108,66 4308,66 4508,66 4708,66 4908,66 5108,66 5308,66 5508,66 408,266 608,266 808,266 1008,266 1208,266 1408,266 5008,266 5208,266 5408,266 5608,266 3865,455 3920,455 108,466 308,466 508,466 708,466 908,466 1108,466 1308,466 1508,466 2708,466 2908,466 3108,466 3308,466 3508,466 3708,466 4108,466 4308,466 4508,466 4708,466 4908,466 5108,466 5308,466 5508,466 5708,466 208,666 408,666 608,666 808,666 1008,666 1208,666 1408,666 1608,666 2008,666 2208,666 3808,666 4208,666 4408,666 4608,666 4808,666 5008,666 5208,666 5408,666 5608,666 5808,666 108,866 1708,866 1908,866 4508,866 4708,866 4908,866 5108,866 5308,866 5508,866 5708,866 1989.58,1017.21 2530,1060 2560,1060 4808,1066 5008,1066 5208,1066 5408,1066 5608,1066 5808,1066 250,1080 340,1080 165,1115 250,1120 340,1120 4300,1135 275,1160 315,1160 4325,1220 4325,1250 308,1266 508,1266 1308,1266 1508,1266 1708,1266 2108,1266 2908,1266 3108,1266 3308,1266 3508,1266 3708,1266 3908,1266 4708,1266 4908,1266 5108,1266 5308,1266 5508,1266 5708,1266 4250,1280 4325,1280 4175,1450 208,1466 1008,1466 1208,1466 1408,1466 1608,1466 1808,1466 2808,1466 3008,1466 3408,1466 3608,1466 4808,1466 5008,1466 5208,1466 5408,1466 5608,1466 5808,1466 4175,1485 4065,1530 2545,1545 4065,1570 2545,1585 108,1666 308,1666 508,1666 708,1666 1108,1666 1308,1666 1508,1666 1708,1666 2108,1666 2508,1666 2908,1666 3108,1666 3308,1666 3508,1666 3708,1666 3908,1666 4508,1666 4708,1666 4908,1666 5108,1666 5308,1666 5508,1666 5708,1666 408,1866 608,1866 808,1866 1008,1866 1208,1866 1408,1866 1608,1866 2608,1866 2808,1866 3008,1866 3208,1866 3408,1866 3608,1866 3808,1866 4208,1866 4408,1866 4808,1866 5008,1866 5208,1866 5408,1866 5608,1866 508,2066 708,2066 908,2066 1108,2066 1308,2066 1508,2066 1708,2066 2508,2066 2708,2066 3108,2066 3308,2066 3508,2066 3708,2066 3908,2066 4108,2066 4308,2066 4508,2066 4708,2066 4908,2066 5108,2066 5308,2066 5508,2066
  other v2: 1937.34,1100
HDC1010_DRDY: J11.20 R37.1 U10.D2 U18.1 | length 1312.1
  Layer 1 - Top Layer w10: R37.1@2521.38,245 2525.32,241.06 U18.1@2525.32,200 J11.20@2450,200 2400,250 2400,455 2420,475 2590,475 2615,500 2615,1105 2600.31,1119.69 U10.D2@2545.32,1119.69
NetC1_1: C1.1 R3.1 R4.2 U1.1 | length 205.9
  Layer 4 - Bottom Layer w15: R4.2@439.53,1100 R3.1@515,1100 520,1105 C1.1@520,1166.38 523.03,1169.41 U1.1@580.71,1169.41
NetC1_2: C1.2 R2.2 | length 45
  Layer 4 - Bottom Layer w15: R2.2@475,1213.62 C1.2@520,1213.62
NetC2_2: C2.2 R5.1 R6.2 U1.3 | length 198
  Layer 4 - Bottom Layer w15: U1.3@580.71,1220.59 580.71,1285.71 R5.1@585,1290 593.5,1298.5 C2.2@593.5,1360 601.38,1367.87 R6.2@601.38,1410
NetC3_2: C3.2 R6.1 | length 71.8
  Layer 4 - Bottom Layer w15: R6.1@648.62,1410 650,1411.38 650,1460 C3.2@665,1475
NetC4_1: C4.1 R14.1 | length 59.9
  Layer 4 - Bottom Layer w15: C4.1@2186.5,825 2195,833.5 R14.1@2195,881.38
NetC5_1: C5.1 R9.1 R10.2 U2.1 | length 228.7
  Layer 4 - Bottom Layer w15: U2.1@4295.71,1404.41 4239.41,1404.41 4225,1390 4228.62,1386.38 C5.1@4228.62,1330 4305,1330 R9.1@4315,1340
NetC5_2: C5.2 R8.2 | length 46.9
  Layer 4 - Bottom Layer w15: R8.2@4180,1283.62 4180,1328.62 C5.2@4181.38,1330
NetC6_2: C6.2 R11.1 R12.2 U2.3 | length 198.8
  Layer 4 - Bottom Layer w15: R12.2@4240,1583.62 4241.38,1585 R11.1@4300,1585 4308.5,1576.5 C6.2@4308.5,1515 4308.5,1488.5 4295.71,1475.71 U2.3@4295.71,1455.59
NetC7_2: C7.2 R12.1 | length 60.6
  Layer 4 - Bottom Layer w15: C7.2@4185,1550 4198.62,1536.38 R12.1@4240,1536.38
NetC8_1: C8.1 R13.1 | length 59.1
  Layer 4 - Bottom Layer w15: R13.1@2243.62,995 2243.62,937.87 C8.1@2245,936.5
NetC9_1: C9.1 R16.2 U3.1 | length 97.2
  Layer 4 - Bottom Layer w15: U3.1@2245.71,1043.82 2249.53,1040 C9.1@2296.38,1040 R16.2@2296.38,995
NetC10_1: C10.1 J5.1 R15.2 R17.1 U3.4 | length 533.8
  Layer 4 - Bottom Layer w15: R17.1@2146.38,1425 2095.75,1425 J5.1@2049.19,1378.44 2042.54,1371.79 C10.1@2042.54,1122.25 2108.91,1122.25 R15.2@2121.65,1134.99 2124.24,1132.4 U3.4@2194.53,1132.4
NetC10_2: C10.2 R13.2 R14.2 R15.1 U3.3 | length 274.9
  Layer 4 - Bottom Layer w15: C10.2@2042.54,1059.25 2117.39,1059.25 R15.1@2121.65,1054.99 2132.82,1043.82 U3.3@2194.53,1043.82 2194.53,996.85 R13.2@2196.38,995 2195,993.62 R14.2@2195,928.62
NetC11_1: C11.1 R18.1 R19.2 U4.3 | length 212.4
  Layer 4 - Bottom Layer w15: U4.3@2300.59,1424.29 2405.71,1424.29 R19.2@2425,1405 R18.1@2425,1325
NetC12_1: C12.1 R20.1 R21.2 U5.1 | length 205.3
  Layer 4 - Bottom Layer w15: U5.1@2300.59,1485.71 2359.33,1485.71 C12.1@2360,1486.38 2423.62,1486.38 R20.1@2425,1485 R21.2@2425,1565
NetC13_1: C13.1 R22.2 U7.4 | length 109.5
  Layer 4 - Bottom Layer w10: C13.1@829.76,1219 886.71,1219 U7.4@887.4,1219.69
  Layer 4 - Bottom Layer w15: R22.2@778.62,1220 828.76,1220 C13.1@829.76,1219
